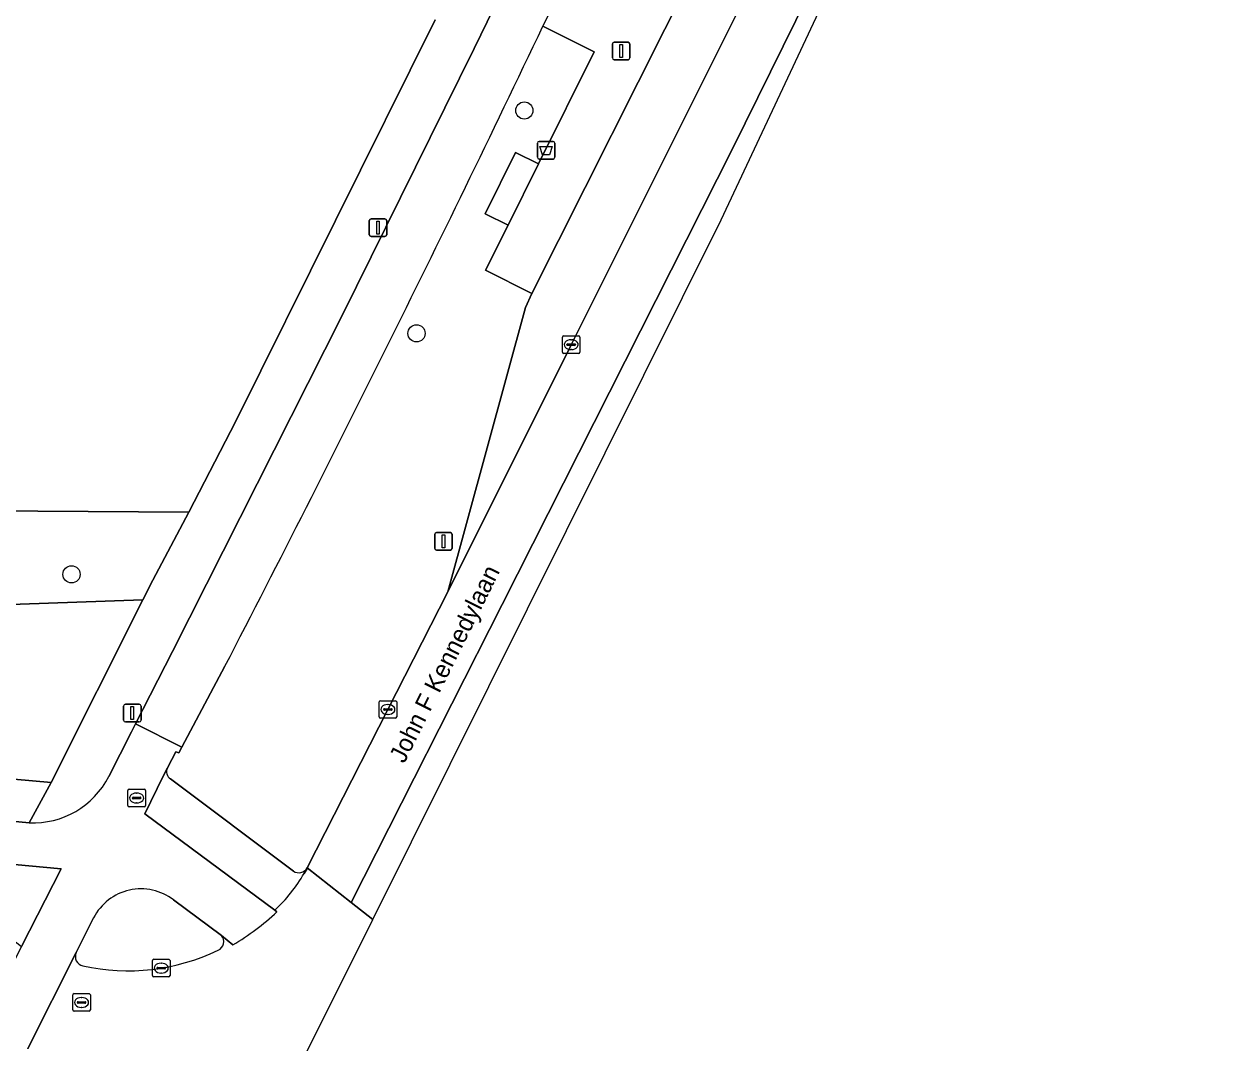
# Model space of a CAD drawing. Extents: x 161241 to 161758, y 384138 to 384885.
# Drawn here: x 161639.9 to 161708.2, y 384599.3 to 384657.2 of the extents above; entities that cross this region are included whole.
import ezdxf

# ---------------------------------------------------------------- set-up
doc = ezdxf.new("R2010")
doc.units = 0
for name, color, linetype in [('IMGEO_Afvalbak', 7, 'Continuous'), ('IMGEO_Berm_groen', 7, 'Continuous'), ('IMGEO_Boom', 7, 'Continuous'), ('IMGEO_Erf', 7, 'Continuous'), ('IMGEO_Fietspad_gesloten', 7, 'Continuous'), ('IMGEO_Groenvoorziening', 7, 'Continuous'), ('IMGEO_Hek', 7, 'Continuous'), ('IMGEO_Kolk', 7, 'Continuous'), ('IMGEO_Lichtmast', 7, 'Continuous'), ('IMGEO_Openbare_ruimte_label', 7, 'Continuous'), ('IMGEO_OVBaan_gesloten', 7, 'Continuous'), ('IMGEO_Rijbaan_lokaal_gesloten', 7, 'Continuous'), ('IMGEO_Rioolput', 7, 'Continuous'), ('IMGEO_Verkeerseiland_gesloten', 7, 'Continuous'), ('IMGEO_Voetpad_gesloten', 7, 'Continuous'), ('IMGEO_Voetpad_open', 7, 'Continuous')]:
    doc.layers.add(name, color=color, linetype=linetype)

msp = doc.modelspace()

# ---------------------------------------------------------------- linework, layer by layer
at = {"layer": 'IMGEO_Afvalbak'}
for p, q in [((161669.103, 384649.619), (161669.103, 384650.419)), ((161669.103, 384650.419), (161669.103, 384649.619)), ((161669.203, 384650.519), (161669.993, 384650.519)), ((161669.993, 384650.519), (161669.203, 384650.519)), ((161670.093, 384650.419), (161670.093, 384649.619)), ((161670.093, 384649.619), (161670.093, 384650.419)), ((161669.993, 384649.519), (161669.203, 384649.519)), ((161669.203, 384649.519), (161669.993, 384649.519))]:
    msp.add_line(p, q, dxfattribs=at)
msp.add_lwpolyline([(161669.246, 384650.233), (161669.95, 384650.233), (161669.801, 384649.763), (161669.395, 384649.763), (161669.246, 384650.233)], dxfattribs=at)
for centre, start, end in [((161669.203, 384650.419), 90, 180), ((161669.203, 384650.419), 90, 180), ((161669.993, 384650.419), 0, 90), ((161669.993, 384650.419), 360, 90), ((161669.203, 384649.619), 180, 270), ((161669.203, 384649.619), 180, 270), ((161669.993, 384649.619), 270, 0), ((161669.993, 384649.619), 270, 0)]:
    msp.add_arc(centre, 0.1, start, end, dxfattribs=at)
at = {"layer": 'IMGEO_Berm_groen'}
for points in [[(161668.425, 384641.073), (161668.794, 384641.885), (161666.149, 384643.196), (161667.442, 384645.768), (161666.144, 384646.412), (161667.864, 384649.891), (161669.17, 384649.244), (161672.338, 384655.608), (161669.414, 384657.064)], [(161656.018, 384609.223), (161660.608, 384618.23), (161664.011, 384624.923), (161668.425, 384641.073)], [(161651.342, 384620.684), (161648.89, 384616.086), (161648.717, 384615.762), (161648.551, 384615.818), (161648.099, 384614.943), (161648.091, 384614.928), (161648.083, 384614.913)], [(161648.258, 384614.28), (161655.238, 384609.045)]]:
    msp.add_lwpolyline(points, dxfattribs=at)
for centre, radius, start, end in [((160576.681, 385177.208), 1210.213, 332.622188, 334.545441), ((161648.522, 384614.694), 0.491, 153.48469, 237.42344), ((161655.548, 384609.485), 0.538, 234.84609, 330.86402)]:
    msp.add_arc(centre, radius, start, end, dxfattribs=at)
at = {"layer": 'IMGEO_Boom'}
for centre in [(161668.362, 384652.278), (161662.235, 384639.611), (161642.628, 384625.912)]:
    msp.add_circle(centre, 0.489, dxfattribs=at)
at = {"layer": 'IMGEO_Erf'}
msp.add_lwpolyline([(161599.011, 384635.9), (161616.903, 384629.956), (161617.828, 384629.647), (161649.293, 384629.449), (161651.971, 384634.614), (161663.295, 384657.439)], dxfattribs=at)
at = {"layer": 'IMGEO_Fietspad_gesloten'}
for points in [[(161670.701, 384666.467), (161665.518, 384655.805), (161657.99, 384640.592), (161648.37, 384621.531), (161646.258, 384617.415), (161648.89, 384616.086), (161651.342, 384620.684)], [(161669.414, 384657.064), (161672.189, 384662.664)], [(161654.299, 384606.723), (161654.174, 384606.822), (161646.797, 384612.297), (161647.827, 384614.44), (161648.083, 384614.913), (161648.091, 384614.928), (161648.099, 384614.943), (161648.551, 384615.818), (161648.717, 384615.762), (161648.89, 384616.086), (161646.258, 384617.415), (161646.043, 384616.951), (161644.74, 384614.42)], [(161640.22, 384611.795), (161632.051, 384612.558), (161631.812, 384612.558)], [(161634.6, 384609.834), (161638.553, 384609.494), (161642.039, 384609.166), (161639.785, 384604.754), (161637.958, 384601.195), (161636.626, 384598.646), (161633.723, 384592.905), (161631.945, 384589.377), (161625.518, 384576.727), (161628.195, 384575.423), (161628.393, 384575.761), (161629.79, 384578.533), (161632.228, 384576.565), (161632.384, 384576.488), (161633.956, 384579.527), (161633.252, 384580.024), (161631.645, 384581.275)], [(161648.422, 384607.4), (161651.142, 384605.383), (161651.799, 384604.852)], [(161640.133, 384598.942), (161640.138, 384598.962), (161642.896, 384604.409), (161643.883, 384606.388)]]:
    msp.add_lwpolyline(points, dxfattribs=at)
for centre, radius, start, end in [((160576.681, 385177.208), 1210.213, 332.622188, 334.545441), ((161640.454, 384616.596), 4.807, 267.21137, 333.08058), ((161646.572, 384605.013), 3.02, 52.22358, 152.91422), ((161644.427, 384617.307), 14.473, 300.6184, 313.00397)]:
    msp.add_arc(centre, radius, start, end, dxfattribs=at)
at = {"layer": 'IMGEO_Groenvoorziening'}
for points in [[(161649.293, 384629.449), (161617.828, 384629.647), (161616.903, 384629.956), (161616.611, 384628.604), (161617.553, 384628.377), (161620.45, 384627.751), (161621.105, 384627.595), (161620.569, 384625.051), (161632.188, 384623.942), (161646.68, 384624.454), (161647.251, 384625.589)], [(161646.68, 384624.454), (161632.188, 384623.942), (161620.569, 384625.051), (161620.151, 384623.067), (161620.103, 384622.856), (161624.217, 384619.712), (161626.391, 384618.043), (161630.208, 384615.091), (161641.462, 384614.077)]]:
    msp.add_lwpolyline(points, close=True, dxfattribs=at)
at = {"layer": 'IMGEO_Hek'}
msp.add_lwpolyline([(161616.903, 384629.956), (161617.828, 384629.647), (161649.293, 384629.449)], dxfattribs=at)
at = {"layer": 'IMGEO_Kolk'}
for p, q in [((161670.523, 384638.54), (161670.523, 384639.392)), ((161670.598, 384639.466), (161671.45, 384639.466)), ((161671.011, 384639.246), (161671.036, 384639.246)), ((161671.524, 384639.392), (161671.524, 384638.54)), ((161671.45, 384638.466), (161670.598, 384638.466)), ((161670.782, 384638.96), (161670.782, 384638.972)), ((161671.22, 384638.923), (161670.822, 384638.923)), ((161670.825, 384639.009), (161671.223, 384639.009)), ((161671.034, 384638.686), (161671.009, 384638.686)), ((161671.266, 384638.972), (161671.266, 384638.96)), ((161660.107, 384617.804), (161660.107, 384618.656)), ((161660.182, 384618.73), (161661.034, 384618.73)), ((161661.108, 384618.656), (161661.108, 384617.804)), ((161660.366, 384618.224), (161660.366, 384618.236)), ((161660.804, 384618.187), (161660.406, 384618.187)), ((161660.409, 384618.273), (161660.807, 384618.273)), ((161660.618, 384617.95), (161660.593, 384617.95)), ((161660.595, 384618.51), (161660.62, 384618.51)), ((161660.85, 384618.236), (161660.85, 384618.224)), ((161661.034, 384617.73), (161660.182, 384617.73)), ((161647.224, 384603.102), (161647.224, 384603.954)), ((161647.299, 384604.028), (161648.151, 384604.028)), ((161647.526, 384603.571), (161647.924, 384603.571)), ((161647.712, 384603.808), (161647.737, 384603.808)), ((161648.225, 384603.954), (161648.225, 384603.102)), ((161648.151, 384603.028), (161647.299, 384603.028)), ((161647.483, 384603.522), (161647.483, 384603.534)), ((161647.921, 384603.485), (161647.523, 384603.485)), ((161647.735, 384603.248), (161647.71, 384603.248)), ((161647.967, 384603.534), (161647.967, 384603.522))]:
    msp.add_line(p, q, dxfattribs=at)
for points in [[(161670.523, 384638.54), (161670.523, 384639.392)], [(161670.598, 384639.466), (161671.45, 384639.466)], [(161671.524, 384639.392), (161671.524, 384638.54)], [(161671.45, 384638.466), (161670.598, 384638.466)], [(161660.107, 384617.804), (161660.107, 384618.656)], [(161660.182, 384618.73), (161661.034, 384618.73)], [(161661.108, 384618.656), (161661.108, 384617.804)], [(161661.034, 384617.73), (161660.182, 384617.73)], [(161647.224, 384603.102), (161647.224, 384603.954)], [(161647.299, 384604.028), (161648.151, 384604.028)], [(161648.225, 384603.954), (161648.225, 384603.102)], [(161648.151, 384603.028), (161647.299, 384603.028)]]:
    msp.add_lwpolyline(points, dxfattribs=at)
for centre, radius, start, end in [((161670.6, 384639.39), 0.0765, 91.55205, 178.44795), ((161670.6, 384639.39), 0.0765, 91.55205, 178.44795), ((161671.448, 384639.39), 0.0765, 1.55205, 88.44795), ((161671.448, 384639.39), 0.0765, 1.55205, 88.44795), ((161670.6, 384638.542), 0.0765, 181.55205, 268.44795), ((161670.6, 384638.542), 0.0765, 181.55205, 268.44795), ((161670.822, 384638.969), 0.0403, 85.87752, 175.75265), ((161670.819, 384638.959), 0.0366, 178.93798, 274.71019), ((161671.223, 384638.966), 0.043, 264.86636, 352.45326), ((161671.227, 384638.971), 0.0386, 1.73085, 96.63898), ((161671.448, 384638.542), 0.0765, 271.55205, 358.44795), ((161671.448, 384638.542), 0.0765, 271.55205, 358.44795), ((161660.184, 384618.654), 0.0765, 91.55205, 178.44795), ((161660.184, 384618.654), 0.0765, 91.55205, 178.44795), ((161661.032, 384618.654), 0.0765, 1.55205, 88.44795), ((161661.032, 384618.654), 0.0765, 1.55205, 88.44795), ((161660.406, 384618.233), 0.0403, 85.87752, 175.75265), ((161660.403, 384618.223), 0.0366, 178.93798, 274.71019), ((161660.807, 384618.23), 0.043, 264.86636, 352.45326), ((161660.811, 384618.235), 0.0386, 1.73085, 96.63898), ((161660.184, 384617.806), 0.0765, 181.55205, 268.44795), ((161660.184, 384617.806), 0.0765, 181.55205, 268.44795), ((161661.032, 384617.806), 0.0765, 271.55205, 358.44795), ((161661.032, 384617.806), 0.0765, 271.55205, 358.44795), ((161647.301, 384603.952), 0.0765, 91.55205, 178.44795), ((161647.301, 384603.952), 0.0765, 91.55205, 178.44795), ((161647.523, 384603.531), 0.0403, 85.87752, 175.75265), ((161647.928, 384603.533), 0.0386, 1.73085, 96.63898), ((161648.149, 384603.952), 0.0765, 1.55205, 88.44795), ((161648.149, 384603.952), 0.0765, 1.55205, 88.44795), ((161647.301, 384603.104), 0.0765, 181.55205, 268.44795), ((161647.301, 384603.104), 0.0765, 181.55205, 268.44795), ((161647.52, 384603.521), 0.0366, 178.93798, 274.71019), ((161647.924, 384603.528), 0.043, 264.86636, 352.45326), ((161648.149, 384603.104), 0.0765, 271.55205, 358.44795), ((161648.149, 384603.104), 0.0765, 271.55205, 358.44795)]:
    msp.add_arc(centre, radius, start, end, dxfattribs=at)
for centre, major_axis, ratio, start_param, end_param in [((161671.01, 384638.966), (-0.387, 0.002), 0.722429, 4.712389, 7.853982), ((161671.035, 384638.966), (-0.39, 0.002), 0.717154, 1.570796, 4.712389), ((161660.594, 384618.23), (-0.387, 0.002), 0.722429, 4.712389, 7.853982), ((161660.619, 384618.23), (-0.39, 0.002), 0.717154, 1.570796, 4.712389), ((161647.711, 384603.528), (-0.387, 0.002), 0.722429, 4.712389, 7.853982), ((161647.736, 384603.528), (-0.39, 0.002), 0.717154, 1.570796, 4.712389)]:
    msp.add_ellipse(centre, major_axis=major_axis, ratio=ratio, start_param=start_param, end_param=end_param, dxfattribs=at)
at = {"layer": 'IMGEO_Lichtmast'}
for p, q in [((161673.468, 384656.164), (161674.258, 384656.164)), ((161674.258, 384656.164), (161673.468, 384656.164)), ((161673.368, 384655.264), (161673.368, 384656.064)), ((161673.368, 384656.064), (161673.368, 384655.264)), ((161674.358, 384656.064), (161674.358, 384655.264)), ((161674.358, 384655.264), (161674.358, 384656.064)), ((161674.258, 384655.164), (161673.468, 384655.164)), ((161673.468, 384655.164), (161674.258, 384655.164)), ((161659.55, 384645.217), (161659.55, 384646.017)), ((161659.55, 384646.017), (161659.55, 384645.217)), ((161659.65, 384646.117), (161660.44, 384646.117)), ((161660.44, 384646.117), (161659.65, 384646.117)), ((161660.54, 384646.017), (161660.54, 384645.217)), ((161660.54, 384645.217), (161660.54, 384646.017)), ((161660.44, 384645.117), (161659.65, 384645.117)), ((161659.65, 384645.117), (161660.44, 384645.117)), ((161663.268, 384627.388), (161663.268, 384628.188)), ((161663.268, 384628.188), (161663.268, 384627.388)), ((161663.368, 384628.288), (161664.158, 384628.288)), ((161664.158, 384628.288), (161663.368, 384628.288)), ((161664.258, 384628.188), (161664.258, 384627.388)), ((161664.258, 384627.388), (161664.258, 384628.188)), ((161664.158, 384627.288), (161663.368, 384627.288)), ((161663.368, 384627.288), (161664.158, 384627.288)), ((161645.585, 384617.626), (161645.585, 384618.426)), ((161645.585, 384618.426), (161645.585, 384617.626)), ((161645.685, 384618.526), (161646.475, 384618.526)), ((161646.475, 384618.526), (161645.685, 384618.526)), ((161646.575, 384618.426), (161646.575, 384617.626)), ((161646.575, 384617.626), (161646.575, 384618.426)), ((161646.475, 384617.526), (161645.685, 384617.526)), ((161645.685, 384617.526), (161646.475, 384617.526))]:
    msp.add_line(p, q, dxfattribs=at)
for points in [[(161673.788, 384656.039), (161673.938, 384656.039), (161673.938, 384655.289), (161673.788, 384655.289), (161673.788, 384656.039)], [(161659.97, 384645.992), (161660.12, 384645.992), (161660.12, 384645.242), (161659.97, 384645.242), (161659.97, 384645.992)], [(161663.688, 384628.163), (161663.838, 384628.163), (161663.838, 384627.413), (161663.688, 384627.413), (161663.688, 384628.163)], [(161646.005, 384618.401), (161646.155, 384618.401), (161646.155, 384617.651), (161646.005, 384617.651), (161646.005, 384618.401)]]:
    msp.add_lwpolyline(points, dxfattribs=at)
for centre, start, end in [((161673.468, 384656.064), 90, 180), ((161673.468, 384656.064), 90, 180), ((161674.258, 384656.064), 0, 90), ((161674.258, 384656.064), 360, 90), ((161673.468, 384655.264), 180, 270), ((161673.468, 384655.264), 180, 270), ((161674.258, 384655.264), 270, 0), ((161674.258, 384655.264), 270, 0), ((161659.65, 384646.017), 90, 180), ((161659.65, 384646.017), 90, 180), ((161660.44, 384646.017), 0, 90), ((161660.44, 384646.017), 360, 90), ((161659.65, 384645.217), 180, 270), ((161659.65, 384645.217), 180, 270), ((161660.44, 384645.217), 270, 0), ((161660.44, 384645.217), 270, 0), ((161663.368, 384628.188), 90, 180), ((161663.368, 384628.188), 90, 180), ((161664.158, 384628.188), 0, 90), ((161664.158, 384628.188), 360, 90), ((161663.368, 384627.388), 180, 270), ((161663.368, 384627.388), 180, 270), ((161664.158, 384627.388), 270, 0), ((161664.158, 384627.388), 270, 0), ((161645.685, 384618.426), 90, 180), ((161645.685, 384618.426), 90, 180), ((161646.475, 384618.426), 0, 90), ((161646.475, 384618.426), 360, 90), ((161645.685, 384617.626), 180, 270), ((161645.685, 384617.626), 180, 270), ((161646.475, 384617.626), 270, 0), ((161646.475, 384617.626), 270, 0)]:
    msp.add_arc(centre, 0.1, start, end, dxfattribs=at)
at = {"layer": 'IMGEO_OVBaan_gesloten'}
msp.add_lwpolyline([(161691.462, 384679.879), (161678.224, 384660.756), (161677.855, 384659.925), (161668.794, 384641.885), (161668.425, 384641.073), (161664.011, 384624.923), (161671.024, 384638.966), (161680.462, 384657.827), (161689.106, 384675.152)], close=True, dxfattribs=at)
at = {"layer": 'IMGEO_Rijbaan_lokaal_gesloten'}
for points in [[(161659.742, 384606.287), (161679.558, 384646.065), (161706.085, 384702.624), (161726.15, 384753.412), (161740.764, 384796.627), (161745.215, 384816.138), (161744.047, 384816.284), (161742.448, 384808.757), (161735.777, 384786.652), (161725.575, 384756.83), (161716.255, 384732.828), (161712.723, 384722.298), (161707.131, 384707.91), (161694.574, 384679.263), (161680.185, 384650.094), (161667.104, 384624.194), (161658.512, 384607.257), (161659.742, 384606.287)], [(161700.185, 384699.405), (161692.45, 384682.113), (161691.462, 384679.879), (161689.106, 384675.152), (161680.462, 384657.827), (161671.024, 384638.966), (161664.011, 384624.923), (161660.608, 384618.23), (161656.018, 384609.223), (161658.512, 384607.257), (161667.104, 384624.194), (161680.185, 384650.094), (161694.574, 384679.263), (161707.131, 384707.91)], [(161640.066, 384566.79), (161648.348, 384583.415), (161659.742, 384606.287), (161658.512, 384607.257), (161656.018, 384609.223), (161656.016, 384609.19), (161655.845, 384608.91)], [(161654.174, 384606.822), (161654.299, 384606.723)], [(161651.799, 384604.852), (161651.142, 384605.383)], [(161642.896, 384604.409), (161640.138, 384598.962), (161640.133, 384598.942)]]:
    msp.add_lwpolyline(points, dxfattribs=at)
for centre, radius, start, end in [((161648.216, 384613.302), 8.803, 312.59298, 330.06733), ((161644.427, 384617.307), 14.473, 300.6184, 313.00397), ((161650.75, 384605.028), 0.529, 293.30803, 42.1398), ((161643.374, 384604.177), 0.531, 154.10586, 258.71947), ((161645.832, 384615.23), 11.854, 257.51894, 295.62742)]:
    msp.add_arc(centre, radius, start, end, dxfattribs=at)
at = {"layer": 'IMGEO_Rioolput'}
for p, q in [((161645.826, 384612.773), (161645.826, 384613.625)), ((161645.901, 384613.699), (161646.753, 384613.699)), ((161646.085, 384613.193), (161646.085, 384613.205)), ((161646.523, 384613.156), (161646.125, 384613.156)), ((161646.128, 384613.242), (161646.526, 384613.242)), ((161646.314, 384613.479), (161646.339, 384613.479)), ((161646.569, 384613.205), (161646.569, 384613.193)), ((161646.827, 384613.625), (161646.827, 384612.773)), ((161646.753, 384612.699), (161645.901, 384612.699)), ((161646.337, 384612.919), (161646.312, 384612.919)), ((161642.695, 384601.15), (161642.695, 384602.002)), ((161642.77, 384602.076), (161643.622, 384602.076)), ((161642.954, 384601.57), (161642.954, 384601.582)), ((161643.392, 384601.533), (161642.994, 384601.533)), ((161642.997, 384601.619), (161643.395, 384601.619)), ((161643.183, 384601.856), (161643.208, 384601.856)), ((161643.438, 384601.582), (161643.438, 384601.57)), ((161643.696, 384602.002), (161643.696, 384601.15)), ((161643.622, 384601.076), (161642.77, 384601.076)), ((161643.206, 384601.296), (161643.181, 384601.296))]:
    msp.add_line(p, q, dxfattribs=at)
for points in [[(161645.826, 384612.773), (161645.826, 384613.625)], [(161645.901, 384613.699), (161646.753, 384613.699)], [(161646.827, 384613.625), (161646.827, 384612.773)], [(161646.753, 384612.699), (161645.901, 384612.699)], [(161642.695, 384601.15), (161642.695, 384602.002)], [(161642.77, 384602.076), (161643.622, 384602.076)], [(161643.696, 384602.002), (161643.696, 384601.15)], [(161643.622, 384601.076), (161642.77, 384601.076)]]:
    msp.add_lwpolyline(points, dxfattribs=at)
for centre, radius, start, end in [((161645.903, 384613.623), 0.0765, 91.55205, 178.44795), ((161645.903, 384613.623), 0.0765, 91.55205, 178.44795), ((161646.125, 384613.202), 0.0403, 85.87752, 175.75265), ((161646.122, 384613.192), 0.0366, 178.93798, 274.71019), ((161646.526, 384613.199), 0.043, 264.86636, 352.45326), ((161646.53, 384613.204), 0.0386, 1.73085, 96.63898), ((161646.751, 384613.623), 0.0765, 1.55205, 88.44795), ((161646.751, 384613.623), 0.0765, 1.55205, 88.44795), ((161645.903, 384612.775), 0.0765, 181.55205, 268.44795), ((161645.903, 384612.775), 0.0765, 181.55205, 268.44795), ((161646.751, 384612.775), 0.0765, 271.55205, 358.44795), ((161646.751, 384612.775), 0.0765, 271.55205, 358.44795), ((161642.772, 384602), 0.0765, 91.55205, 178.44795), ((161642.772, 384602), 0.0765, 91.55205, 178.44795), ((161642.994, 384601.579), 0.0403, 85.87752, 175.75265), ((161642.991, 384601.569), 0.0366, 178.93798, 274.71019), ((161643.395, 384601.576), 0.043, 264.86636, 352.45326), ((161643.399, 384601.581), 0.0386, 1.73085, 96.63898), ((161643.62, 384602), 0.0765, 1.55205, 88.44795), ((161643.62, 384602), 0.0765, 1.55205, 88.44795), ((161642.772, 384601.152), 0.0765, 181.55205, 268.44795), ((161642.772, 384601.152), 0.0765, 181.55205, 268.44795), ((161643.62, 384601.152), 0.0765, 271.55205, 358.44795), ((161643.62, 384601.152), 0.0765, 271.55205, 358.44795)]:
    msp.add_arc(centre, radius, start, end, dxfattribs=at)
for centre, major_axis, ratio, start_param, end_param in [((161646.313, 384613.199), (-0.387, 0.002), 0.722429, 4.712389, 7.853982), ((161646.338, 384613.199), (-0.39, 0.002), 0.717154, 1.570796, 4.712389), ((161643.182, 384601.576), (-0.387, 0.002), 0.722429, 4.712389, 7.853982), ((161643.207, 384601.576), (-0.39, 0.002), 0.717154, 1.570796, 4.712389)]:
    msp.add_ellipse(centre, major_axis=major_axis, ratio=ratio, start_param=start_param, end_param=end_param, dxfattribs=at)
at = {"layer": 'IMGEO_Verkeerseiland_gesloten'}
for points in [[(161651.142, 384605.383), (161648.422, 384607.4)], [(161643.883, 384606.388), (161642.896, 384604.409)]]:
    msp.add_lwpolyline(points, dxfattribs=at)
for centre, radius, start, end in [((161646.572, 384605.013), 3.02, 52.22358, 152.91422), ((161650.75, 384605.028), 0.529, 293.30803, 42.1398), ((161643.374, 384604.177), 0.531, 154.10586, 258.71947), ((161645.832, 384615.23), 11.854, 257.51894, 295.62742)]:
    msp.add_arc(centre, radius, start, end, dxfattribs=at)
at = {"layer": 'IMGEO_Voetpad_gesloten'}
msp.add_lwpolyline([(161669.17, 384649.244), (161667.864, 384649.891), (161666.144, 384646.412), (161667.442, 384645.768)], close=True, dxfattribs=at)
at = {"layer": 'IMGEO_Voetpad_open'}
for points in [[(161644.74, 384614.42), (161646.043, 384616.951), (161646.258, 384617.415), (161648.37, 384621.531), (161657.99, 384640.592), (161665.518, 384655.805), (161670.701, 384666.467)], [(161663.295, 384657.439), (161651.971, 384634.614), (161649.293, 384629.449), (161647.251, 384625.589), (161646.68, 384624.454), (161641.462, 384614.077), (161640.22, 384611.795)], [(161641.462, 384614.077), (161630.208, 384615.091), (161626.391, 384618.043), (161624.217, 384619.712), (161620.103, 384622.856), (161620.151, 384623.067), (161618.573, 384623.427), (161618.136, 384621.395), (161621.959, 384618.479), (161624.731, 384616.32), (161627.429, 384614.233)], [(161648.083, 384614.913), (161647.827, 384614.44), (161646.797, 384612.297), (161654.174, 384606.822)], [(161631.812, 384612.558), (161632.051, 384612.558), (161640.22, 384611.795), (161641.462, 384614.077)], [(161655.238, 384609.045), (161648.258, 384614.28)], [(161637.219, 384606.741), (161639.785, 384604.754), (161642.039, 384609.166), (161638.553, 384609.494)], [(161655.845, 384608.91), (161656.016, 384609.19), (161656.018, 384609.223)]]:
    msp.add_lwpolyline(points, dxfattribs=at)
msp.add_lwpolyline([(161677.855, 384659.925), (161672.189, 384662.664), (161669.414, 384657.064), (161672.338, 384655.608), (161669.17, 384649.244), (161667.442, 384645.768), (161666.149, 384643.196), (161668.794, 384641.885)], close=True, dxfattribs=at)
for centre, radius, start, end in [((161648.522, 384614.694), 0.491, 153.48469, 237.42344), ((161640.454, 384616.596), 4.807, 267.21137, 333.08058), ((161655.548, 384609.485), 0.538, 234.84609, 330.86402), ((161648.216, 384613.302), 8.803, 312.59298, 330.06733)]:
    msp.add_arc(centre, radius, start, end, dxfattribs=at)

# ---------------------------------------------------------------- texts
at = {"layer": 'IMGEO_Openbare_ruimte_label'}
msp.add_text('John F Kennedylaan', height=1, rotation=63.56313, dxfattribs=at).set_placement((161661.536, 384615.117))

doc.saveas('drawing.dxf')
